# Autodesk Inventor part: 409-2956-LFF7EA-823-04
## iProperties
Created: 2010-09
Part Number: 409-2956-LFF7EA-823-04
Material: 3/8" OD TUBE - SS
Document SubType Name: Modeling
Designer: S. Boerckel
Engineer: Steve Boerckel
Mass: 61.6007 g
Surface Area: 127.01 cm^2
Volume: 7.62385 cm^3
Density: 8.08 g/cm^3
Description: PRESSURE DIFF TUBE
Length: 10.844 in
Author: S. Boerckel
Revision Number: 0
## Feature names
1. Sweep3
